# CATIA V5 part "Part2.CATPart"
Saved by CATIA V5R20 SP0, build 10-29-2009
Part number: Part2
Bounding box of the stored display mesh (mm): x -270 to 60, y -60 to 60, z -20 to 350
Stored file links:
  C:\Users\Orange\Desktop\Assembly Design-5\Part2.CATPart
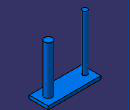
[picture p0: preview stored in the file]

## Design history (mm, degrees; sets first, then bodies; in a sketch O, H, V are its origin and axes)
Body1 (main body)
  DatumSurface1
  Sketch1 on face of DatumSurface1, origin (0, 0, 0), H (1, 0, 0), V (0, 1, 0)
    line L1 (-270, 60) -> (60, 60)
    line L2 (60, 60) -> (60, -60)
    line L3 (60, -60) -> (-270, -60)
    line L4 (-270, -60) -> (-270, 60)
    horizontal: L1 H, L3 H
    vertical: L2 V, L4 V
  Pad1: profile Sketch1, direction (0, 0, -1), length 20
  DatumCurve1
  Sketch2 on end face of Pad1, origin (0, 0, -20), H (1, 0, 0), V (0, -1, 0)
    circle A1 centre (0, 0) radius 25
  Pad2: profile Sketch2, direction (0, 0, 1), length 320
  Sketch3 on start face of Pad1, origin (0, 0, 0), H (1, 0, 0), V (0, 1, 0)
    circle A1 centre (-230, 0) radius 15
    point P1 (-230, 0)
    radius A1 = 15
    coincidence: P1 H
  Pad3: profile Sketch3, direction (0, 0, 1), length 350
